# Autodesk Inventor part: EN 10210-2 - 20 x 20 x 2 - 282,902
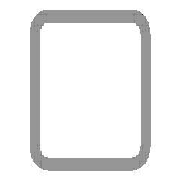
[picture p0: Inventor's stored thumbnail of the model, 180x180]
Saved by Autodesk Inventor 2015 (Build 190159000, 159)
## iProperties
_CCFamilyMember: 1
_CCFamilyDisplayName: DIN EN 10210-2 (Square) - Tube
_FrameMemberDoc: Frame Member File
_Version: 15.0.0
_GetPNFromCC: 1
Created: 2015-05
Part Number: EN 10210-2 - 20 x 20 x 2 - 282,902
Material: Steel, Mild
Description: Tube
Document SubType Name: Modeling
Standard: DIN
Designer: TREINA6
Standard Revision: 1997
Standards Organization: DIN
Language: en-US
Size Designation: 20 x 20 x 2
Categories: <MemberInstance><Categories><Category DisplayName="Structural Shapes" InternalName="089c4875-fa83-4c05-b084-43b9cc11f5ed" Mnemonic="GRDR"><CategoryParameter Dis
Stock Number: 20 x 20 x 2
Density: 7.85 g/cm^3
Appearance: Semi-Polished
IsCustomPart: 1
G_L: 282,902 mm
G_W: 20,000 mm
G_H: 20,000 mm
+45447D7F-895F-4506-8804-617C93922C5F+CUTDETAIL1: Miter 60,00 deg
+FA3F2EE0-632E-44FE-9EA9-D751984C1BD8+CUTDETAIL2: Miter 60,00 deg
Author: TREINA6
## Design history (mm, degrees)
node "Start plane"
node "End plane"
sketch "Sketch"
  geometry: L1 (-10, -7)-(-10, 7); L2 (-7, 10)-(7, 10); L3 (10, 7)-(10, -7); L4 (7, -10)-(-7, -10); L5 (-7, 8)-(7, 8); L6 (8, 7)-(8, -7); L7 (7, -8)-(-7, -8); L8 (-8, -7)-(-8, 7); L9 (0, 14.87)-(0, -14.87) reference; L10 (-14.87, 0)-(14.87, 0) reference; A1 r 3 centre (-7, -7) between (-10, -7) and (-7, -10); A2 r 3 centre (-7, 7) between (-7, 10) and (-10, 7); A3 r 3 centre (7, 7) between (10, 7) and (7, 10); A4 r 3 centre (7, -7) between (7, -10) and (10, -7); A5 r 1 centre (-7, 7) between (-7, 8) and (-8, 7); A6 r 1 centre (7, 7) between (8, 7) and (7, 8); A7 r 1 centre (7, -7) between (7, -8) and (8, -7); A8 r 1 centre (-7, -7) between (-8, -7) and (-7, -8)
  constraints: 16 end point, 16 point on circle, 8 centre point, 8 tangent, 4 parallel, 3 equal radius, 2 perpendicular, 7 other
  dimensions: "d7" = 3 radius of A1 (= G_IR); "d10" = 20 distance between parallel lines of L2 L4 (= G_H); "d11" = 20 distance between parallel lines of L1 L3 (= G_W); "d12" = 2 distance between parallel lines of L3 L6 (= G_T); "d15" = 10 distance between parallel lines of L2 L10 (= 0.5 x d10); "d16" = 10 distance between parallel lines of L9 L3 (= 0.5 x d11)
extrude "Body" new body sketch "Sketch" stored distance "d3" = 282.90163 (= G_L); taper "d4" = 0 deg
node "Driven Length"
  sketch "Sketch3"
    geometry: L1 (0, 0)-(10, 0) reference
    constraints: 2 end point, 1 horizontal
  workplane "Work Plane3"
  sketch "Sketch4"
    geometry: L1 (-2, 0)-(12, 0) reference; L2 (-2, 282.902)-(12, 282.902) reference
    dimensions: "d18" = 282.90163 distance between parallel lines of L1 L2 (derived)
workplane "Work Plane4"
split "Split1"
workplane "Work Plane5"
split "Split2"
body "Solid1"
other parameters: "G_W" = 20 [user parameter; used in 1 equation term], "G_H" = 20 [user parameter; used in 1 equation term], "G_T" = 2 [user parameter; used in 1 equation term], "G_IR" = 3 [user parameter; used in 1 equation term], "G_L" = 282.90163 (= d18) [user parameter; used in 1 equation term], "G_OFFSET_START" = 0 [user parameter; used in 1 equation term], "G_OFFSET_END" = 0 [user parameter; used in 1 equation term], "d13" = 0 (computed from G_OFFSET_START), "d14" = 282.90163 (= G_OFFSET_END + B_L), "B_L" = 282.90163 [user parameter; used in 1 equation term], "d17" = 90 deg
